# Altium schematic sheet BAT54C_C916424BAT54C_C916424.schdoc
size 127 x 101 mm
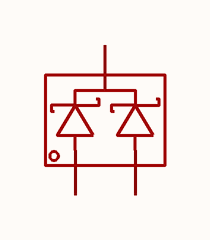
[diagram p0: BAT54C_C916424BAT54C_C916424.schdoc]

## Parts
D?  bat54c_c916424  [SOT-23-3_L2.9-W1.3-P1.90-LS2.4-BR]  (value not drawn)

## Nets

Not connected (* = marked no-connect by the designer): D? 1 2 3

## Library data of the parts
D? = bat54c_c916424: 二极管配置:1对共阴极;正向压降(Vf):1V@100mA;直流反向耐压(Vr):30V;整流电流:200mA;; Manufacturer: JSMSEMI(杰盛微); ManufacturerPart: BAT54C; AddInBom: yes; ModelId: c62791f0466c4ae2a892c056b845b0ca; ModelName: SOT-23-3P_L2.9-W1.3-H1.0-LS2.4-P0.95; ModelTransform: 98.425,114.173,0,180,0,0,0.0005,-0.0005,0; Diode Configuration: 1对共阴极; Voltage - DC Reverse(Vr): 30V; Current - Rectified: 200mA; Reverse Leakage Current (Ir): 2uA@25V; Non-Repetitive Peak Forward Surge Current: 600mA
